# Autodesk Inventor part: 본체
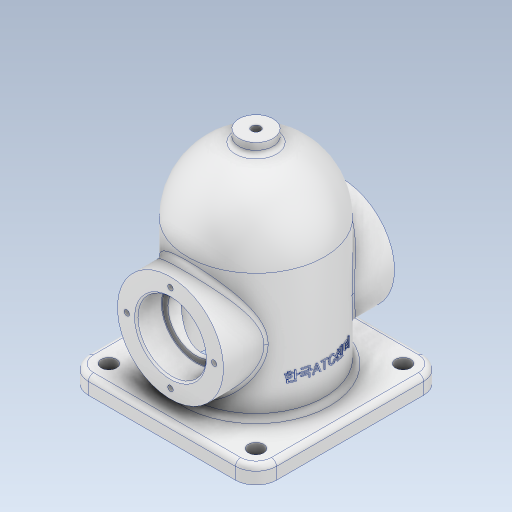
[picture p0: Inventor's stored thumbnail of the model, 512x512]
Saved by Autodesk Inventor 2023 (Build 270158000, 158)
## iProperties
Created: 2025-04
Part Number: 본체
Material: 알루미늄 6061
Document SubType Name: Modeling
Designer: Admin
Density: 2.7 g/cm^3
Appearance: 알루미늄 - 평지
Mass: 867.781 g
Surface Area: 792.5 cm^2
Volume: 321.4 cm^3
Author: Admin
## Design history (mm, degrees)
sketch "스케치2"
  geometry: L1 (0, 42)-(40, 42); L2 (40, 42)-(40, -42); L3 (40, -42)-(0, -42); L4 (0, -42)-(0, 42); L5 (-9.657, 0)-(57.941, 0) reference; L6 (0, 82)-(0, 42); L7 (0, -68.457)-(0, 116.741) reference; A1 r 40 centre (0, 42) between (40, 42) and (0, 82); 2 further points
  constraints: 10 end point, 2 parallel, 2 point on circle, 1 centre point, 1 coincident, 1 horizontal, 1 midpoint, 1 perpendicular, 1 vertical
  dimensions: "d5" = 40 distance of L2.end L3.end; "d6" = 84 distance of L1.end L2.end; "d7" = 42 distance between parallel lines of L5 L1
revolve "회전1" sketch "스케치2" stored, may be unused: angle "d8" = 90 deg
sketch "스케치3"
  geometry: L1 (0, -67.8)-(0, 112.8) reference; L2 (40, -42)-(-40, -42) reference; C1 r 31 at (0, 6); 1 further point
  constraints: 1 centre point, 1 coincident, 1 point on line
  dimensions: "d9" = 62 diameter of C1; "d22" = 48 distance from line of L2 point (0, 6)
extrude "돌출1" join sketch "스케치3" stored distance "d10" = 100; taper "d11" = 0 deg
sketch "스케치4"
  geometry: L1 (-55, -55)-(55, -55); L2 (55, -55)-(55, 55); L3 (55, 55)-(-55, 55); L4 (-55, 55)-(-55, -55); L5 (-55, -55)-(55, 55); L6 (55, -55)-(-55, 55); 1 further point
  constraints: 12 end point, 2 midpoint, 2 parallel, 1 horizontal, 1 perpendicular
  dimensions: "d12" = 110 distance of L3.end L2.end; "d13" = 110 distance of L2.end L1.end
extrude "돌출2" join sketch "스케치4" distance "d14" = 10; taper "d15" = 0 deg
sketch "스케치5"
  geometry: C1 r 10 at (55, -55); 1 further point
  constraints: 1 centre point, 1 coincident
  dimensions: "d16" = 20 diameter of C1
extrude "돌출3" join sketch "스케치5" distance "d17" = 129; taper "d18" = 0 deg
sketch "스케치6"
  geometry: L1 (42, -40)-(42, 40) reference; L2 (42, -32)-(-42, -32); L3 (-42, 55)-(-42, -55) reference; L4 (-42, 0)-(-42, -32); L5 (-42, 0)-(74, 0); A1 r 32 centre (42, 0) between (42, -32) and (74, 0); 2 further points
  constraints: 6 end point, 2 perpendicular, 2 point on circle, 2 point on line, 1 centre point, 1 horizontal, 1 midpoint
  dimensions: "d19" = 32 radius of A1; "d20" = 84 distance of L2.start L2.end
revolve "회전2" sketch "스케치6" stored, may be unused: angle "d21" = 90 deg
sketch "스케치7"
  geometry: L1 (37, 50)-(-25, 50) reference; L2 (6, 50)-(6, -50); L3 (-25, -50)-(37, -50) reference; L4 (6, 50)-(26, 50); L5 (26, 50)-(26, 35); L6 (26, 35)-(6, 35); L7 (6, 35)-(6, 50); L8 (6, -50)-(26, -50); L9 (26, -50)-(26, -35); L10 (26, -35)-(6, -35); L11 (6, -35)-(6, -50); L12 (6, 35)-(22.5, 35); L13 (22.5, 35)-(22.5, -35); L14 (22.5, -35)-(6, -35); L15 (6, -35)-(6, 35); L16 (-67.8, 0)-(112.8, 0) reference; 4 further points
  constraints: 26 end point, 6 parallel, 3 horizontal, 3 perpendicular, 2 midpoint, 2 point on line, 1 other
  dimensions: "d23" = 40 diameter of L5 L2; "d24" = 33 diameter of L13 L2; "d25" = 15 distance between parallel lines of L4 L12
revolve "회전3" sketch "스케치7" stored, may be unused: angle "d26" = 90 deg
sketch "스케치8"
  geometry: L1 (-43, -43)-(43, -43); L2 (43, -43)-(43, 43); L3 (43, 43)-(-43, 43); L4 (-43, 43)-(-43, -43); L5 (-43, -43)-(43, 43); L6 (43, -43)-(-43, 43); C1 r 4.5 at (-43, -43); 1 further point
  constraints: 12 end point, 2 midpoint, 2 parallel, 1 centre point, 1 coincident, 1 horizontal, 1 perpendicular
  dimensions: "d27" = 86 distance of L3.end L2.end; "d28" = 86 distance of L2.end L1.end; "d29" = 9 diameter of C1
extrude "돌출4" cut sketch "스케치8" extent not by distance; stored distance "d30" = 0; taper "d31" = 0 deg
sketch "스케치9"
  geometry: 2 further points
  constraints: 1 coincident
hole "구멍1" sketch "스케치9" at (0, 0) diameter "d38" = 5.1881; stored, may be unused: countersink angle "d42" = 90 deg, drill point angle "d44" = 0 deg; dims "d39" = 12, "d40" = 4, "d41" = 2, "d43" = 16
fillet "모깎기1" dims "d45" = 12
fillet "모깎기2" dims "d46" = 3
chamfer "모따기1" distance "d47" = 1; stored, may be unused: second distance "d48" = 2, angle "d49" = 45 deg
fillet "모깎기3" dims "d50" = 0.3
fillet "모깎기4" dims "d51" = 3
node "작업 평면1"
sketch "스케치10"
  geometry: L1 (-42, -43)-(-42, 43) reference; L2 (-67.8, 0)-(112.8, 0) reference; 2 further points
  constraints: 1 point on line, 1 other
  dimensions: "d53" = 30 distance from line of L1 point (-12, 0)
feature "엠보싱1" sketch "스케치10" dims "d5" = 40, "d6" = 84, "d7" = 42, "d14" = 10, "d54" = 0.5, "d55" = 0
sketch "스케치11" dims "d56" = 51
  geometry: L1 (0, -73.8)-(0, 106.8) reference; L2 (43, -48)-(-43, -48) reference; 3 further points
  constraints: 2 point on line, 1 vertical alignment, 2 other
  dimensions: "d57" = 48 distance from line of L2 point (0, 0)
hole "구멍2" sketch "스케치11" at (0, 25.5) diameter "d58" = 3.242; stored, may be unused: countersink angle "d62" = 90 deg, drill point angle "d64" = 118 deg; dims "d59" = 8, "d60" = 4, "d61" = 2, "d63" = 10
node "솔리드1"
pattern_linear "직사각형 패턴1" dims "d34" = 86, "d37" = 86
pattern_circular "원형 패턴1" dims angle "d66" = 360 deg
mirror "미러1"
feature "A9D066F2-1C7D-4E18-AEED-F7BC21143FA4" dims "d38" = 5.1881, "d39" = 12, "d40" = 4, "d41" = 2, "d42" = 90 deg, "d43" = 16, "d44" = 0
other parameters: "d52" = 46.0375
